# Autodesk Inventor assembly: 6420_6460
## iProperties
Author: Ole Germer
Shininess: 64.0
Angle Display Precision: 2
Document Length Units: 11272
Document Angle Units: 11286
Document Time Units: 11279
Document Mass Units: 11290
Document Length Units Precision: 3
Document Angle Units Precision: 2
Compacted: True
PropertySet Name: _Private Model Information
Created: 2002-10
Part Number: 6420_6460
Document SubType Name: Assembly
Designer: Ole Germer
Control State: 0
Master: False
Checked Out: False
PropertySet Name: Design Tracking Control
Density: 0.0
Volumn: 0.0
Area: 0.0
PropertySet Name: Model Information
